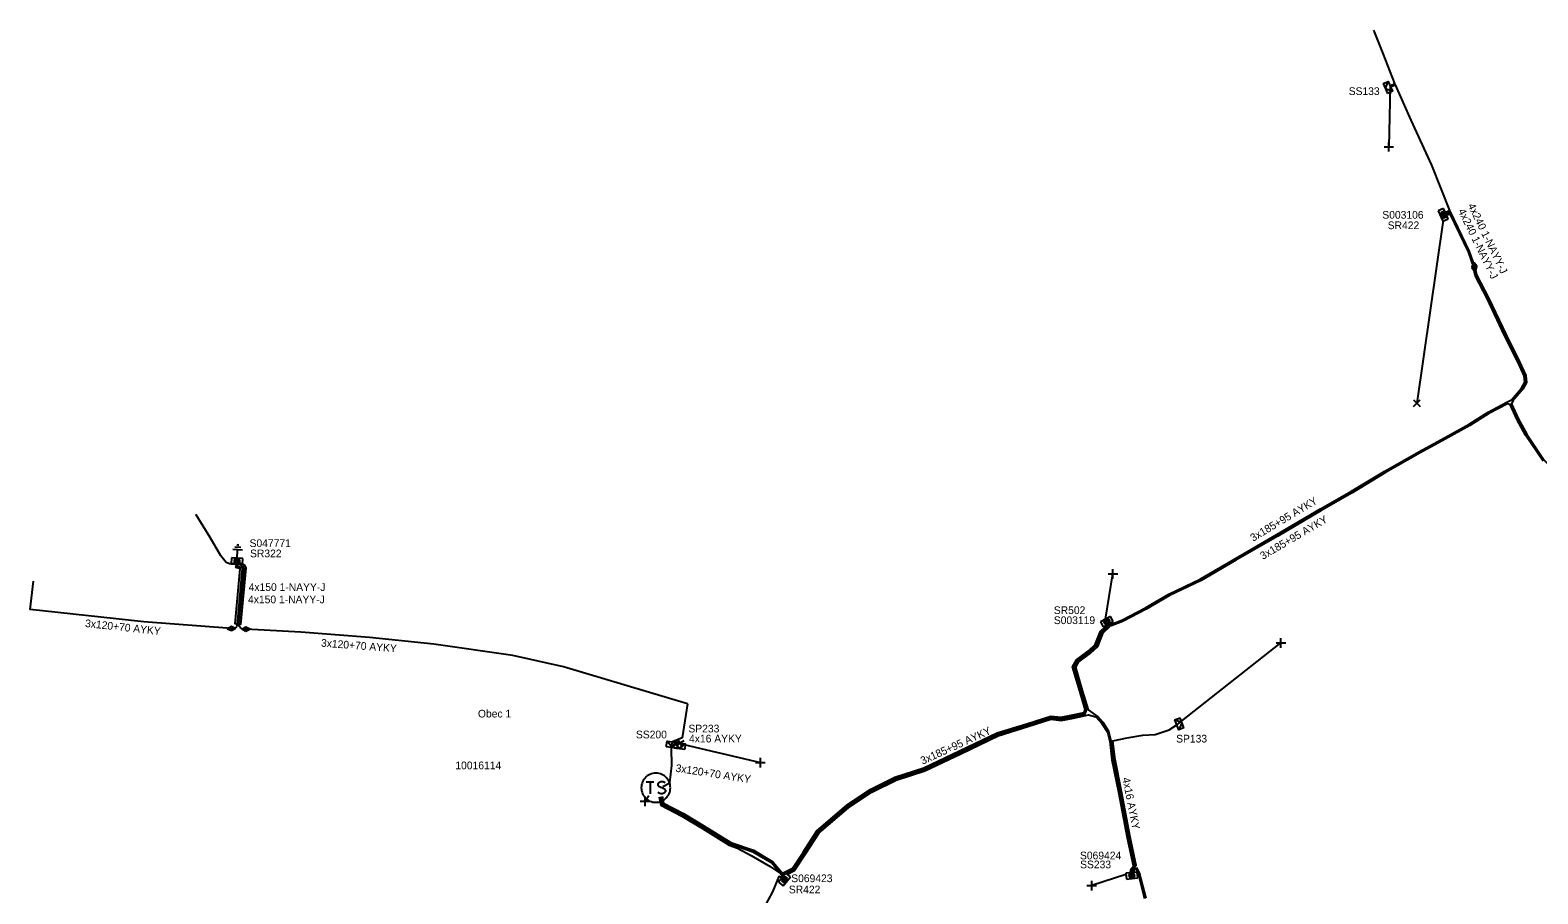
# Model space of a CAD drawing. Extents: x -763093 to -760976, y -1155572 to -1152009.
# Drawn here: x -762945 to -762749.4, y -1152180.3 to -1152068.2 of the extents above; entities that cross this region are included whole.
import ezdxf

# ---------------------------------------------------------------- set-up
doc = ezdxf.new("R2010")
doc.units = 0
for name, color, linetype in [('Vrstva 1', 7, 'Continuous'), ('Vrstva 14', 7, 'Continuous'), ('Vrstva 15', 7, 'Continuous'), ('Vrstva 19', 7, 'Continuous'), ('Vrstva 20', 7, 'Continuous'), ('Vrstva 25', 7, 'Continuous'), ('Vrstva 26', 7, 'Continuous'), ('Vrstva 27', 7, 'Continuous'), ('Vrstva 28', 7, 'Continuous'), ('Vrstva 29', 7, 'Continuous'), ('Vrstva 30', 7, 'Continuous'), ('Vrstva 31', 7, 'Continuous'), ('Vrstva 33', 7, 'Continuous'), ('Vrstva 34', 7, 'Continuous'), ('Vrstva 4', 7, 'Continuous'), ('Vrstva 5', 7, 'Continuous'), ('Vrstva 52', 7, 'Continuous'), ('Vrstva 54', 7, 'Continuous'), ('Vrstva 59', 7, 'Continuous'), ('Vrstva 6', 7, 'Continuous'), ('Vrstva 8', 7, 'Continuous'), ('Vrstva 9', 7, 'Continuous')]:
    doc.layers.add(name, color=color, linetype=linetype)

# ---------------------------------------------------------------- blocks, each defined once
blk = doc.blocks.new('NN870')
at = {"layer": 'Vrstva 4'}
for points in [[(0, -0.25), (0.5, 0), (0, 0.25), (-0.5, 0), (0, -0.25)], [(0.37, 0), (0, 0.19), (-0.36, 0), (0, -0.19), (0.37, 0)], [(0.24, 0), (0, 0.12), (-0.25, 0), (0, -0.12), (0.24, 0)], [(0.12, 0), (0, 0.06), (-0.13, 0), (0, -0.06), (0.12, 0)]]:
    blk.add_lwpolyline(points, dxfattribs=at)
blk = doc.blocks.new('NN800')
at = {"layer": 'Vrstva 1'}
for points in [[(-0.44, 0.44), (0.44, -0.44)], [(-0.44, -0.44), (0.44, 0.44)]]:
    blk.add_lwpolyline(points, dxfattribs=at)
blk = doc.blocks.new('NN620')
at = {"layer": 'Vrstva 8'}
for points in [[(0.75, 0), (-0.75, 0)], [(-0.75, 0), (-0.75, -0.75)], [(0.75, -0.75), (0.75, 0)], [(-0.75, -0.75), (0.75, -0.75)], [(0.37, -0.18), (-0.38, -0.18)], [(-0.38, -0.18), (-0.38, -0.56)], [(-0.38, -0.56), (0.37, -0.56)], [(0.32, -0.23), (-0.33, -0.23)], [(-0.33, -0.23), (-0.33, -0.51)], [(-0.33, -0.51), (0.32, -0.51)], [(0.27, -0.27), (-0.28, -0.27)], [(-0.28, -0.27), (-0.28, -0.46)], [(-0.28, -0.46), (0.27, -0.46)], [(0.23, -0.32), (-0.23, -0.32)], [(-0.23, -0.32), (-0.23, -0.42)], [(-0.23, -0.42), (0.23, -0.42)], [(-0.19, -0.37), (0.19, -0.37)], [(0.23, -0.42), (0.23, -0.32)], [(0.27, -0.46), (0.27, -0.27)], [(0.32, -0.51), (0.32, -0.23)], [(0.37, -0.56), (0.37, -0.18)]]:
    blk.add_lwpolyline(points, dxfattribs=at)
blk = doc.blocks.new('NN630')
at = {"layer": 'Vrstva 9'}
for points in [[(0, -0.7), (-0.7, 0)], [(-0.7, -0.7), (-0.7, 0), (0.7, 0), (0.7, -0.7)], [(-0.7, -0.7), (0.7, -0.7)], [(0, -0.7), (0.7, 0)]]:
    blk.add_lwpolyline(points, dxfattribs=at)
blk = doc.blocks.new('NN810')
at = {"layer": 'Vrstva 14'}
for points in [[(0.63, -1.89), (-0.62, -1.89)], [(0, -0.64), (0, -1.89)], [(0.39, -2.2), (-0.4, -2.2)], [(0, -2.52), (-0.12, -2.52)], [(0.14, -2.52), (0, -2.52)]]:
    blk.add_lwpolyline(points, dxfattribs=at)
blk = doc.blocks.new('NN610')
at = {"layer": 'Vrstva 6'}
for points in [[(1.88, 0), (1.87, 0.2), (1.84, 0.39), (1.79, 0.58), (1.72, 0.77), (1.63, 0.94), (1.52, 1.11), (1.4, 1.26), (1.26, 1.4), (1.1, 1.53), (0.94, 1.63), (0.76, 1.72), (0.58, 1.8), (0.19, 1.88), (0.19, 1.88), (-0.01, 1.89), (-0.21, 1.88), (-0.4, 1.85), (-0.59, 1.8), (-0.78, 1.72), (-0.95, 1.63), (-1.12, 1.53), (-1.27, 1.4), (-1.41, 1.26), (-1.54, 1.11), (-1.64, 0.94), (-1.73, 0.77), (-1.8, 0.58), (-1.86, 0.39), (-1.89, 0.2), (-1.9, 0), (-1.89, -0.2), (-1.86, -0.39), (-1.8, -0.58), (-1.73, -0.77), (-1.64, -0.95), (-1.54, -1.11), (-1.41, -1.27), (-1.27, -1.41), (-1.12, -1.53), (-0.95, -1.64), (-0.78, -1.73), (-0.59, -1.8), (-0.4, -1.85), (-0.21, -1.88), (-0.01, -1.89), (0.19, -1.88), (0.39, -1.85), (0.58, -1.8), (0.76, -1.73), (0.94, -1.64), (1.1, -1.53), (1.26, -1.41), (1.4, -1.27), (1.52, -1.11), (1.63, -0.95), (1.72, -0.77), (1.79, -0.58), (1.84, -0.39), (1.87, -0.2), (1.88, 0)], [(-1.27, 0.78), (-0.26, 0.78)], [(-0.76, 0.78), (-0.76, -0.79)], [(1.19, 0.66), (0.94, 0.78), (0.62, 0.78), (0.37, 0.66), (0.24, 0.47), (0.24, 0.4), (0.37, 0.22), (1.12, -0.16), (1.25, -0.32), (1.25, -0.48), (1.12, -0.67), (0.87, -0.79), (0.62, -0.79), (0.49, -0.73), (0.24, -0.6)]]:
    blk.add_lwpolyline(points, dxfattribs=at)

msp = doc.modelspace()

# ---------------------------------------------------------------- linework, layer by layer
at = {"layer": 'Vrstva 20'}
msp.add_lwpolyline([(-762918.11, -1152137.3), (-762917.43, -1152137.49), (-762917.15, -1152137.67), (-762917, -1152138.04), (-762917.68, -1152145.35), (-762918.37, -1152145.29), (-762917.71, -1152138.14), (-762918.3, -1152137.98)], close=True, dxfattribs=at)
at = {"layer": 'Vrstva 5'}
for points in [[(-762761.37, -1152091.87), (-762760.76, -1152091.65), (-762763.13, -1152085.77), (-762765.81, -1152079.91), (-762767.82, -1152075.35), (-762768.18, -1152075.5), (-762768.5, -1152075.53), (-762768.27, -1152075.33), (-762767.9, -1152075.17), (-762769.42, -1152071.28), (-762770.64, -1152068.23)], [(-762757.52, -1152098.92), (-762758.21, -1152096.94), (-762760.69, -1152091.82), (-762761.29, -1152092.05)], [(-762761.22, -1152092.24), (-762760.79, -1152092.08), (-762758.39, -1152097.02), (-762757.7, -1152098.98)], [(-762862.99, -1152167.66), (-762862.79, -1152168.53), (-762860.23, -1152169.9), (-762857.56, -1152171.48), (-762854.07, -1152173.66), (-762851.12, -1152174.67), (-762848.63, -1152176.15), (-762847.37, -1152177.65), (-762846.07, -1152177), (-762844.7, -1152174.91), (-762842.89, -1152172.15), (-762839.02, -1152168.83), (-762835.98, -1152166.79), (-762832.78, -1152165.19), (-762829.03, -1152163.98), (-762824.42, -1152161.77), (-762819.51, -1152159.44), (-762815.67, -1152158.24), (-762812.57, -1152157.27), (-762811.21, -1152157.41), (-762809.68, -1152157.1), (-762808.23, -1152156.8), (-762808.09, -1152156.38), (-762808.8, -1152154.03), (-762809.75, -1152150.86), (-762809.23, -1152149.93), (-762807.66, -1152148.77), (-762806.8, -1152147.97), (-762806.09, -1152146.24), (-762805.5, -1152145.65), (-762804.89, -1152145.41), (-762803.34, -1152144.81), (-762800.26, -1152143.18), (-762797.26, -1152141.43), (-762793.16, -1152139.47), (-762788.63, -1152136.84), (-762783.21, -1152133.7), (-762777.56, -1152130.37), (-762773.55, -1152128.08), (-762769.21, -1152125.47), (-762764.72, -1152122.91), (-762761.47, -1152121.13), (-762758.27, -1152119.35), (-762755.8, -1152117.82), (-762753.37, -1152116.53), (-762752.76, -1152116.2), (-762751.48, -1152114.71), (-762751.04, -1152113.92), (-762751.13, -1152113.1), (-762751.9, -1152111.35), (-762753.67, -1152107.87), (-762755.94, -1152103.06), (-762757.49, -1152100.08), (-762757.7, -1152098.98)], [(-762757.52, -1152098.92), (-762757.31, -1152100), (-762755.76, -1152102.98), (-762753.49, -1152107.79), (-762751.72, -1152111.27), (-762750.93, -1152113.04), (-762750.84, -1152113.96), (-762751.32, -1152114.83), (-762752.61, -1152116.33), (-762752.79, -1152116.74), (-762751.88, -1152118.72), (-762750.77, -1152120.68), (-762748.53, -1152124.03), (-762746.06, -1152126.63), (-762743.8, -1152129.35), (-762742.04, -1152132.07), (-762740.21, -1152135.47), (-762739.01, -1152138), (-762737.83, -1152139.89), (-762737.95, -1152140.3)], [(-762748.69, -1152124.15), (-762750.95, -1152120.78), (-762752.06, -1152118.82), (-762752.97, -1152116.82), (-762753.31, -1152116.73), (-762755.7, -1152118), (-762758.17, -1152119.53), (-762761.37, -1152121.31), (-762764.62, -1152123.09), (-762769.11, -1152125.65), (-762773.45, -1152128.26), (-762777.46, -1152130.55), (-762783.11, -1152133.88), (-762788.53, -1152137.02), (-762793.06, -1152139.65), (-762797.16, -1152141.61), (-762800.16, -1152143.36), (-762803.26, -1152144.99), (-762804.72, -1152145.55), (-762804.9, -1152145.22)], [(-762918.31, -1152137.5), (-762918.86, -1152137.48), (-762919.13, -1152137.5), (-762919.56, -1152137.3), (-762920.23, -1152136.47), (-762921.62, -1152134.06), (-762923.44, -1152131.14), (-762923.47, -1152131.08)], [(-762918.11, -1152137.52), (-762918.12, -1152137.78), (-762917.62, -1152137.92), (-762917.53, -1152137.98), (-762917.47, -1152138.11), (-762918.14, -1152145.31), (-762918.22, -1152145.68), (-762918.46, -1152145.87), (-762918.86, -1152145.89)], [(-762916.98, -1152145.97), (-762917.41, -1152145.97), (-762917.68, -1152145.8), (-762917.82, -1152145.62), (-762917.9, -1152145.33), (-762917.23, -1152138.07), (-762917.33, -1152137.82), (-762917.52, -1152137.7), (-762917.89, -1152137.59), (-762917.89, -1152137.54)], [(-762918.86, -1152145.89), (-762930.23, -1152145.01), (-762944.98, -1152143.42), (-762944.56, -1152139.76)], [(-762859.7, -1152155.67), (-762875.8, -1152150.86), (-762882.34, -1152149.37), (-762892.62, -1152147.91), (-762900.95, -1152147.03), (-762909.87, -1152146.35), (-762916.98, -1152145.97)], [(-762863.18, -1152167.7), (-762862.96, -1152168.66), (-762860.33, -1152170.07), (-762857.66, -1152171.65), (-762854.18, -1152173.83), (-762851.2, -1152174.85), (-762848.77, -1152176.31), (-762847.92, -1152177.31), (-762847.33, -1152177.85), (-762845.93, -1152177.15), (-762844.53, -1152175.02), (-762842.74, -1152172.28), (-762838.9, -1152168.99), (-762835.88, -1152166.96), (-762832.7, -1152165.38), (-762828.96, -1152164.17), (-762824.33, -1152161.95), (-762819.44, -1152159.63), (-762815.61, -1152158.43), (-762812.55, -1152157.47), (-762811.2, -1152157.61), (-762809.64, -1152157.3), (-762808.08, -1152156.97), (-762807.88, -1152156.38), (-762808.61, -1152153.97), (-762809.53, -1152150.88), (-762809.08, -1152150.06), (-762807.53, -1152148.92), (-762806.63, -1152148.09), (-762805.92, -1152146.35), (-762805.24, -1152145.67), (-762805.36, -1152145.45)], [(-762802.26, -1152177.57), (-762802.12, -1152177.05), (-762801.68, -1152176.59), (-762802.45, -1152173.02), (-762803.59, -1152167.08), (-762804.42, -1152162.91), (-762804.71, -1152160.51), (-762805.03, -1152159.27), (-762805.76, -1152158.07), (-762806.45, -1152157.31), (-762807.66, -1152156.42), (-762808.42, -1152153.91), (-762809.31, -1152150.9), (-762808.93, -1152150.19), (-762807.4, -1152149.07), (-762806.46, -1152148.21), (-762805.75, -1152146.46), (-762804.95, -1152145.66), (-762805.11, -1152145.32)], [(-762859.7, -1152155.67), (-762860.39, -1152160.05), (-762861.65, -1152160.58)], [(-762846.82, -1152177.82), (-762845.79, -1152177.3), (-762844.36, -1152175.13), (-762842.59, -1152172.41), (-762838.78, -1152169.15), (-762835.78, -1152167.13), (-762832.62, -1152165.57), (-762828.89, -1152164.36), (-762824.24, -1152162.13), (-762819.37, -1152159.82), (-762815.55, -1152158.62), (-762812.53, -1152157.67), (-762811.19, -1152157.81), (-762809.6, -1152157.5), (-762807.65, -1152157.08), (-762806.7, -1152157.33), (-762805.92, -1152158.19), (-762805.21, -1152159.35), (-762804.91, -1152160.53), (-762804.62, -1152162.94), (-762803.79, -1152167.12), (-762802.65, -1152173.06), (-762801.88, -1152176.63), (-762801.54, -1152177.06), (-762801.21, -1152177.67), (-762800.39, -1152180.93)], [(-762862.89, -1152166.4), (-762862, -1152165.9), (-762861.74, -1152163.65), (-762861.75, -1152161.37), (-762861.65, -1152160.58)], [(-762863.37, -1152167.74), (-762863.13, -1152168.79), (-762860.43, -1152170.24), (-762857.76, -1152171.82), (-762854.27, -1152174.01), (-762853.2, -1152174.38), (-762851.44, -1152175.36), (-762848.97, -1152176.78), (-762847.61, -1152177.67), (-762847.3, -1152178.13)], [(-762800.19, -1152180.89), (-762801.03, -1152177.59), (-762801.35, -1152176.99), (-762801.7, -1152177.06), (-762801.86, -1152177.53)], [(-762847.4, -1152178.23), (-762847.82, -1152178.07), (-762848.67, -1152180.05), (-762849.79, -1152182.14)]]:
    msp.add_lwpolyline(points, dxfattribs=at)
at = {"layer": 'Vrstva 52'}
for points in [[(-762802.08, -1152177.54), (-762801.93, -1152177.11), (-762801.47, -1152176.63), (-762802.25, -1152172.98), (-762803.39, -1152167.04), (-762804.22, -1152162.88), (-762804.51, -1152160.47), (-762802.65, -1152160.07), (-762800.62, -1152159.74), (-762799.03, -1152159.62), (-762797.2, -1152159.02), (-762796.19, -1152158.38)], [(-762861.65, -1152160.58), (-762861.33, -1152160.53), (-762860.94, -1152160.58), (-762860.67, -1152160.76)]]:
    msp.add_lwpolyline(points, dxfattribs=at)
at = {"layer": 'Vrstva 59'}
for points in [[(-762768.5, -1152075.53), (-762768.69, -1152083.38)], [(-762761.63, -1152092.91), (-762765.06, -1152116.63)], [(-762805.45, -1152144.69), (-762804.5, -1152138.8)], [(-762796.19, -1152158.38), (-762782.69, -1152147.75)], [(-762861.65, -1152160.58), (-762850.24, -1152163.28)], [(-762864.7, -1152167.6), (-762865.2, -1152168.3)], [(-762802.81, -1152177.8), (-762807.25, -1152179.25)]]:
    msp.add_lwpolyline(points, dxfattribs=at)

# ---------------------------------------------------------------- block references
at = {"layer": 'Vrstva 15', "rotation": 176.68221935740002}
msp.add_blockref('NN810', (-762918.17, -1152137.52), dxfattribs=at)
at = {"layer": 'Vrstva 19'}
for p, rotation in [((-762757.7, -1152098.98), -79.15351959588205), ((-762757.52, -1152098.92), -79.30569240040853), ((-762918.86, -1152145.89), 2.8624055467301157)]:
    msp.add_blockref('NN870', p, dxfattribs=dict(at, rotation=rotation))
msp.add_blockref('NN870', (-762916.98, -1152145.97), dxfattribs=at)
at = {"layer": 'Vrstva 25'}
msp.add_blockref('NN610', (-762863.79, -1152166.55), dxfattribs=at)
at = {"layer": 'Vrstva 28'}
for p, rotation in [((-762761.29, -1152092.05), -65.82089283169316), ((-762918.17, -1152137.52), 176.68221935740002), ((-762805.11, -1152145.32), -152.75140232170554), ((-762802.08, -1152177.57), 6.457788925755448), ((-762847.4, -1152178.23), 50.96450952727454)]:
    msp.add_blockref('NN620', p, dxfattribs=dict(at, rotation=rotation))
at = {"layer": 'Vrstva 31'}
for p, rotation in [((-762768.5, -1152075.53), -66.79435557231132), ((-762796.19, -1152158.38), 111.11982408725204), ((-762861.65, -1152160.58), -7.682269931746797), ((-762860.67, -1152160.76), -6.8477025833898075)]:
    msp.add_blockref('NN630', p, dxfattribs=dict(at, rotation=rotation))
at = {"layer": 'Vrstva 34'}
for p, rotation in [((-762768.69, -1152083.38), 44.99999995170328), ((-762804.5, -1152138.8), 45), ((-762782.69, -1152147.75), 44.99999995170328), ((-762860.67, -1152160.76), -13.29892853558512), ((-762850.24, -1152163.28), 45), ((-762865.2, -1152168.3), 44.99999995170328), ((-762807.25, -1152179.25), 45)]:
    msp.add_blockref('NN800', p, dxfattribs=dict(at, rotation=rotation))
msp.add_blockref('NN800', (-762765.06, -1152116.63), dxfattribs=at)

# ---------------------------------------------------------------- texts
at = {"layer": 'Vrstva 26'}
msp.add_text('10016114', height=1, dxfattribs=at).set_placement((-762889.81, -1152164.15))
at = {"layer": 'Vrstva 27'}
msp.add_text('Obec 1', height=1, dxfattribs=at).set_placement((-762886.88, -1152157.43))
at = {"layer": 'Vrstva 29'}
for s, p in [('S003106', (-762769.54, -1152092.7)), ('S047771', (-762916.51, -1152135.31)), ('S003119', (-762812.16, -1152145.31)), ('S069424', (-762808.77, -1152175.84)), ('S069423', (-762846.23, -1152178.8))]:
    msp.add_text(s, height=1, dxfattribs=at).set_placement(p)
at = {"layer": 'Vrstva 30'}
for s, p in [('SR422', (-762768.84, -1152094.06)), ('SR322', (-762916.45, -1152136.64)), ('SR502', (-762812.16, -1152144.01)), ('SS233', (-762808.75, -1152177)), ('SR422', (-762846.54, -1152180.25))]:
    msp.add_text(s, height=1, dxfattribs=at).set_placement(p)
at = {"layer": 'Vrstva 33'}
for s, p in [('SS133', (-762773.9, -1152076.65)), ('SS200', (-762866.38, -1152160.14)), ('SP233', (-762859.57, -1152159.37)), ('SP133', (-762796.29, -1152160.68))]:
    msp.add_text(s, height=1, dxfattribs=at).set_placement(p)
at = {"layer": 'Vrstva 54'}
msp.add_text('4x16 AYKY', height=1, dxfattribs=at).set_placement((-762859.49, -1152160.67))
msp.add_text('4x16 AYKY', height=1, rotation=281.256, dxfattribs=at).set_placement((-762803.28, -1152165.32))
at = {"layer": 'Vrstva 6'}
for s, rotation, p in [('4x240 1-NAYY-J', 295.85, (-762758.48, -1152090.99)), ('4x240 1-NAYY-J', 295.933, (-762759.74, -1152091.69)), ('3x185+95 AYKY', 30.887, (-762786.31, -1152134.64)), ('3x185+95 AYKY', 30.353, (-762785.04, -1152136.99)), ('3x120+70 AYKY', 353.847, (-762937.89, -1152145.68)), ('3x120+70 AYKY', 355.641, (-762907.27, -1152148.23)), ('3x185+95 AYKY', 24.385, (-762829.19, -1152163.56)), ('3x120+70 AYKY', 351.265, (-762861.29, -1152164.46))]:
    msp.add_text(s, height=1, rotation=rotation, dxfattribs=at).set_placement(p)
for p in [(-762916.63, -1152141.01), (-762916.71, -1152142.61)]:
    msp.add_text('4x150 1-NAYY-J', height=1, dxfattribs=at).set_placement(p)

doc.saveas('drawing.dxf')
